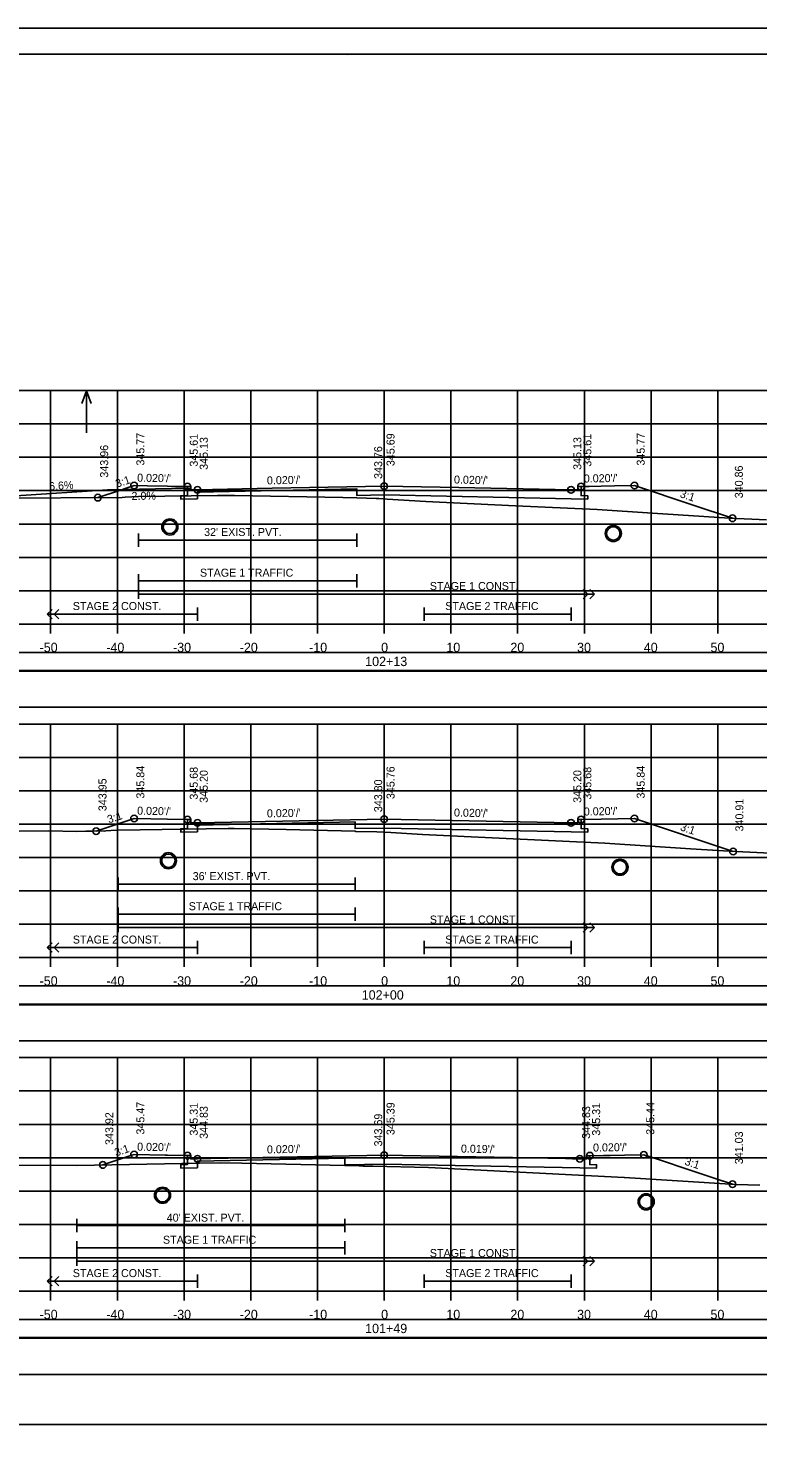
# Model space of a CAD drawing. Extents: x 1368122 to 1710785, y 373130 to 557566.
# Drawn here: x 1368635.5 to 1368744.9, y 373560 to 373770.3 of the extents above; entities that cross this region are included whole.
import ezdxf

# ---------------------------------------------------------------- set-up
doc = ezdxf.new("R2010")
doc.units = 0
for name, color, linetype in [('R_Alt Surface', 7, 'Continuous'), ('R_Axis', 7, 'Continuous'), ('R_Axis Annot', 7, 'Continuous'), ('R_Border', 7, 'Continuous'), ('R_Drive', 7, 'Continuous'), ('R_Exist Surface', 7, 'Continuous'), ('R_Fin Surface', 7, 'Continuous'), ('R_Grid', 7, 'Continuous'), ('R_No Plot', 7, 'Continuous'), ('R_Striping', 7, 'Continuous'), ('R_Water', 7, 'Continuous'), ('R_Water Annot', 7, 'Continuous'), ('R_Xsect Elev', 7, 'Continuous'), ('R_Xsect Slope', 7, 'Continuous')]:
    doc.layers.add(name, color=color, linetype=linetype)

msp = doc.modelspace()

# ---------------------------------------------------------------- linework, layer by layer
at = {"layer": 'R_Alt Surface'}
for points in [[(1368718.38, 373701.59), (1368718.38, 373700.25), (1368719.38, 373700.23), (1368719.38, 373699.73), (1368716.88, 373699.78), (1368688.88, 373700.34), (1368684.8, 373700.26), (1368684.8, 373701.26), (1368660.88, 373700.78), (1368660.88, 373699.78), (1368660.88, 373699.78), (1368658.38, 373699.73), (1368658.38, 373700.23), (1368659.38, 373700.25), (1368659.38, 373701.59)], [(1368652.05, 373694.59), (1368652.05, 373692.59)], [(1368684.8, 373694.59), (1368684.8, 373692.59)], [(1368652.05, 373693.59), (1368684.8, 373693.59)], [(1368718.38, 373651.67), (1368718.38, 373650.32), (1368719.38, 373650.3), (1368719.38, 373649.8), (1368716.88, 373649.85), (1368688.88, 373650.41), (1368684.51, 373650.33), (1368684.51, 373651.33), (1368660.88, 373650.86), (1368660.88, 373649.86), (1368660.88, 373649.85), (1368658.38, 373649.8), (1368658.38, 373650.3), (1368659.38, 373650.32), (1368659.38, 373651.67)], [(1368648.98, 373643), (1368648.98, 373641)], [(1368648.98, 373642), (1368684.51, 373642)], [(1368684.51, 373643), (1368684.51, 373641)], [(1368719.7, 373601.29), (1368719.7, 373599.95), (1368720.72, 373599.93), (1368720.72, 373599.43), (1368718.18, 373599.48), (1368688.88, 373600.04), (1368682.97, 373599.93), (1368682.97, 373600.93), (1368660.88, 373600.49), (1368660.88, 373599.49), (1368660.88, 373599.48), (1368658.38, 373599.43), (1368658.38, 373599.93), (1368659.38, 373599.95), (1368659.38, 373601.3)], [(1368642.78, 373591.8), (1368642.78, 373589.8)], [(1368642.78, 373590.8), (1368682.97, 373590.8)], [(1368682.97, 373591.8), (1368682.97, 373589.8)]]:
    msp.add_lwpolyline(points, dxfattribs=at)
for points in [[(1368539.73, 373674.03), (1368838.03, 373674.03), (1368838.03, 373676.74), (1368539.73, 373676.74)], [(1368539.73, 373668.51), (1368838.03, 373668.51), (1368838.03, 373673.92), (1368539.73, 373673.92)], [(1368539.73, 373624.03), (1368838.03, 373624.03), (1368838.03, 373626.74), (1368539.73, 373626.74)], [(1368539.73, 373618.51), (1368838.03, 373618.51), (1368838.03, 373623.92), (1368539.73, 373623.92)], [(1368539.73, 373574.03), (1368838.03, 373574.03), (1368838.03, 373576.74), (1368539.73, 373576.74)], [(1368539.73, 373568.51), (1368838.03, 373568.51), (1368838.03, 373573.92), (1368539.73, 373573.92)]]:
    msp.add_lwpolyline(points, close=True, dxfattribs=at)
at = {"layer": 'R_Axis'}
for p, q in [((1368538.88, 373680.99), (1368838.88, 373680.99)), ((1368638.88, 373679.59), (1368638.88, 373680.99)), ((1368648.88, 373679.59), (1368648.88, 373680.99)), ((1368658.88, 373679.59), (1368658.88, 373680.99)), ((1368668.88, 373679.59), (1368668.88, 373680.99)), ((1368678.88, 373679.59), (1368678.88, 373680.99)), ((1368688.88, 373679.59), (1368688.88, 373680.99)), ((1368698.88, 373679.59), (1368698.88, 373680.99)), ((1368708.88, 373679.59), (1368708.88, 373680.99)), ((1368718.88, 373679.59), (1368718.88, 373680.99)), ((1368728.88, 373679.59), (1368728.88, 373680.99)), ((1368738.88, 373679.59), (1368738.88, 373680.99)), ((1368538.88, 373630.99), (1368838.88, 373630.99)), ((1368638.88, 373629.59), (1368638.88, 373630.99)), ((1368648.88, 373629.59), (1368648.88, 373630.99)), ((1368658.88, 373629.59), (1368658.88, 373630.99)), ((1368668.88, 373629.59), (1368668.88, 373630.99)), ((1368678.88, 373629.59), (1368678.88, 373630.99)), ((1368688.88, 373629.59), (1368688.88, 373630.99)), ((1368698.88, 373629.59), (1368698.88, 373630.99)), ((1368708.88, 373629.59), (1368708.88, 373630.99)), ((1368718.88, 373629.59), (1368718.88, 373630.99)), ((1368728.88, 373629.59), (1368728.88, 373630.99)), ((1368738.88, 373629.59), (1368738.88, 373630.99)), ((1368538.88, 373580.99), (1368838.88, 373580.99)), ((1368638.88, 373579.59), (1368638.88, 373580.99)), ((1368648.88, 373579.59), (1368648.88, 373580.99)), ((1368658.88, 373579.59), (1368658.88, 373580.99)), ((1368668.88, 373579.59), (1368668.88, 373580.99)), ((1368678.88, 373579.59), (1368678.88, 373580.99)), ((1368688.88, 373579.59), (1368688.88, 373580.99)), ((1368698.88, 373579.59), (1368698.88, 373580.99)), ((1368708.88, 373579.59), (1368708.88, 373580.99)), ((1368718.88, 373579.59), (1368718.88, 373580.99)), ((1368728.88, 373579.59), (1368728.88, 373580.99)), ((1368738.88, 373579.59), (1368738.88, 373580.99))]:
    msp.add_line(p, q, dxfattribs=at)
at = {"layer": 'R_Border'}
for p, q in [((1368530.88, 373766.45), (1368847.06, 373766.45)), ((1368683.4, 373766.19), (1368683.4, 373766.19)), ((1368683.4, 373766.19), (1368683.4, 373766.19)), ((1368847.06, 373560.99), (1368530.88, 373560.99))]:
    msp.add_line(p, q, dxfattribs=at)
at = {"layer": 'R_Drive'}
for p, q in [((1368647.38, 373701.1), (1368633.68, 373700.2)), ((1368659.38, 373701.34), (1368647.38, 373701.1)), ((1368659.88, 373701.09), (1368659.38, 373701.34))]:
    msp.add_line(p, q, dxfattribs=at)
at = {"layer": 'R_Exist Surface'}
for points in [[(1368631.1, 373699.84), (1368649.61, 373699.97), (1368650.07, 373699.99), (1368652.05, 373700.09), (1368663.91, 373700.24), (1368666.45, 373700.28), (1368682.69, 373699.95), (1368684.8, 373699.9), (1368687.67, 373699.8), (1368688.07, 373699.8), (1368689.3, 373699.72), (1368695.11, 373699.35), (1368708.57, 373698.73), (1368720.8, 373698.17), (1368729.09, 373697.62), (1368740.62, 373696.87), (1368746.19, 373696.6)], [(1368634.17, 373649.95), (1368638.58, 373649.98), (1368642.78, 373649.91), (1368644.13, 373649.93), (1368645.31, 373649.92), (1368646.45, 373649.97), (1368646.88, 373649.96), (1368647.13, 373649.99), (1368647.9, 373650.06), (1368648.98, 373650.11), (1368665.5, 373650.34), (1368666.4, 373650.35), (1368674.19, 373650.17), (1368684.51, 373649.92), (1368684.65, 373649.91), (1368687.75, 373649.86), (1368689.89, 373649.72), (1368694.64, 373649.42), (1368706.1, 373648.88), (1368721.93, 373648.14), (1368734.79, 373647.31), (1368740.6, 373646.93), (1368755.01, 373646.23)], [(1368613.1, 373599.99), (1368642.78, 373599.83), (1368661.2, 373600.18), (1368664.37, 373600.24), (1368667.54, 373600.17), (1368682.97, 373599.83), (1368685.14, 373599.77), (1368685.71, 373599.74), (1368687.19, 373599.72), (1368695.53, 373599.53), (1368724.86, 373598.03), (1368724.87, 373598.02), (1368724.91, 373598.02), (1368741.59, 373596.99), (1368745.19, 373596.86)]]:
    msp.add_lwpolyline(points, dxfattribs=at)
for centre in [(1368656.75, 373695.55), (1368723.22, 373694.57), (1368656.53, 373645.51), (1368724.22, 373644.53), (1368655.65, 373595.36), (1368728.14, 373594.38)]:
    msp.add_circle(centre, 1.21, dxfattribs=at)
at = {"layer": 'R_Fin Surface'}
for points in [[(1368645.95, 373699.94), (1368648.13, 373700.67), (1368651.38, 373701.75), (1368653.38, 373701.71), (1368656.38, 373701.65), (1368657.58, 373701.63), (1368659.38, 373701.59), (1368659.58, 373701.59), (1368659.88, 373701.59), (1368659.88, 373701.29), (1368659.88, 373701.09), (1368660.28, 373701.1), (1368660.88, 373701.11), (1368672.08, 373701.34), (1368688.88, 373701.67), (1368700.08, 373701.45), (1368716.88, 373701.11), (1368717.28, 373701.1), (1368717.88, 373701.09), (1368717.88, 373701.39), (1368717.88, 373701.59), (1368718.08, 373701.59), (1368718.38, 373701.59), (1368719.58, 373701.62), (1368721.38, 373701.65), (1368723.38, 373701.69), (1368726.38, 373701.75), (1368735.19, 373698.81), (1368741.09, 373696.85)], [(1368645.7, 373649.94), (1368651.38, 373651.83), (1368656.38, 373651.73), (1368659.38, 373651.67), (1368659.88, 373651.67), (1368659.88, 373651.17), (1368660.88, 373651.19), (1368688.88, 373651.75), (1368716.88, 373651.19), (1368717.88, 373651.17), (1368717.88, 373651.67), (1368718.38, 373651.67), (1368721.38, 373651.73), (1368726.38, 373651.83), (1368741.17, 373646.9)], [(1368646.72, 373599.9), (1368651.05, 373601.35), (1368651.38, 373601.46), (1368656.02, 373601.36), (1368656.38, 373601.36), (1368659.17, 373601.3), (1368659.38, 373601.3), (1368659.84, 373601.3), (1368659.88, 373601.3), (1368659.88, 373600.83), (1368659.88, 373600.8), (1368659.95, 373600.8), (1368660.88, 373600.82), (1368662.88, 373600.86), (1368688.88, 373601.38), (1368708.09, 373601.01), (1368716.07, 373600.86), (1368717.11, 373600.84), (1368718.19, 373600.82), (1368719.06, 373600.8), (1368719.2, 373600.79), (1368719.2, 373600.87), (1368719.2, 373601.29), (1368719.28, 373601.29), (1368719.7, 373601.29), (1368721.74, 373601.33), (1368722.74, 373601.34), (1368724.89, 373601.38), (1368727.81, 373601.43), (1368729.69, 373600.8), (1368735.04, 373599.03), (1368739.68, 373597.49), (1368739.71, 373597.48), (1368739.72, 373597.48), (1368741.1, 373597.02)]]:
    msp.add_lwpolyline(points, dxfattribs=at)
at = {"layer": 'R_Grid'}
for p, q in [((1368538.88, 373715.99), (1368838.88, 373715.99)), ((1368638.88, 373680.99), (1368638.88, 373715.99)), ((1368648.88, 373680.99), (1368648.88, 373715.99)), ((1368658.88, 373680.99), (1368658.88, 373715.99)), ((1368668.88, 373680.99), (1368668.88, 373715.99)), ((1368678.88, 373680.99), (1368678.88, 373715.99)), ((1368688.88, 373680.99), (1368688.88, 373715.99)), ((1368698.88, 373680.99), (1368698.88, 373715.99)), ((1368708.88, 373680.99), (1368708.88, 373715.99)), ((1368718.88, 373680.99), (1368718.88, 373715.99)), ((1368728.88, 373680.99), (1368728.88, 373715.99)), ((1368738.88, 373680.99), (1368738.88, 373715.99)), ((1368538.88, 373710.99), (1368838.88, 373710.99)), ((1368538.88, 373705.99), (1368838.88, 373705.99)), ((1368538.88, 373700.99), (1368838.88, 373700.99)), ((1368538.88, 373695.99), (1368838.88, 373695.99)), ((1368538.88, 373690.99), (1368838.88, 373690.99)), ((1368538.88, 373685.99), (1368838.88, 373685.99)), ((1368538.88, 373680.99), (1368838.88, 373680.99)), ((1368538.88, 373665.99), (1368838.88, 373665.99)), ((1368638.88, 373630.99), (1368638.88, 373665.99)), ((1368648.88, 373630.99), (1368648.88, 373665.99)), ((1368658.88, 373630.99), (1368658.88, 373665.99)), ((1368668.88, 373630.99), (1368668.88, 373665.99)), ((1368678.88, 373630.99), (1368678.88, 373665.99)), ((1368688.88, 373630.99), (1368688.88, 373665.99)), ((1368698.88, 373630.99), (1368698.88, 373665.99)), ((1368708.88, 373630.99), (1368708.88, 373665.99)), ((1368718.88, 373630.99), (1368718.88, 373665.99)), ((1368728.88, 373630.99), (1368728.88, 373665.99)), ((1368738.88, 373630.99), (1368738.88, 373665.99)), ((1368538.88, 373660.99), (1368838.88, 373660.99)), ((1368538.88, 373655.99), (1368838.88, 373655.99)), ((1368538.88, 373650.99), (1368838.88, 373650.99)), ((1368538.88, 373645.99), (1368838.88, 373645.99)), ((1368538.88, 373640.99), (1368838.88, 373640.99)), ((1368538.88, 373635.99), (1368838.88, 373635.99)), ((1368538.88, 373630.99), (1368838.88, 373630.99)), ((1368538.88, 373615.99), (1368838.88, 373615.99)), ((1368638.88, 373580.99), (1368638.88, 373615.99)), ((1368648.88, 373580.99), (1368648.88, 373615.99)), ((1368658.88, 373580.99), (1368658.88, 373615.99)), ((1368668.88, 373580.99), (1368668.88, 373615.99)), ((1368678.88, 373580.99), (1368678.88, 373615.99)), ((1368688.88, 373580.99), (1368688.88, 373615.99)), ((1368698.88, 373580.99), (1368698.88, 373615.99)), ((1368708.88, 373580.99), (1368708.88, 373615.99)), ((1368718.88, 373580.99), (1368718.88, 373615.99)), ((1368728.88, 373580.99), (1368728.88, 373615.99)), ((1368738.88, 373580.99), (1368738.88, 373615.99)), ((1368538.88, 373610.99), (1368838.88, 373610.99)), ((1368538.88, 373605.99), (1368838.88, 373605.99)), ((1368538.88, 373600.99), (1368838.88, 373600.99)), ((1368538.88, 373595.99), (1368838.88, 373595.99)), ((1368538.88, 373590.99), (1368838.88, 373590.99)), ((1368538.88, 373585.99), (1368838.88, 373585.99)), ((1368538.88, 373580.99), (1368838.88, 373580.99))]:
    msp.add_line(p, q, dxfattribs=at)
at = {"layer": 'R_No Plot'}
msp.add_line((1368518.48, 373770.34), (1368851.81, 373770.34), dxfattribs=at)
for points in [[(1368518.47, 373770.34), (1368851.81, 373770.34), (1368851.81, 373557), (1368518.47, 373557)], [(1368764.8, 373766.45), (1368784.42, 373766.45), (1368784.42, 373756.57), (1368800.53, 373756.57), (1368823.73, 373756.57), (1368823.85, 373728.41), (1368847.06, 373728.41), (1368847.06, 373560.99), (1368530.88, 373560.99), (1368530.88, 373766.45)]]:
    msp.add_lwpolyline(points, close=True, dxfattribs=at)
for centre in [(1368651.38, 373701.75), (1368688.88, 373701.67), (1368726.38, 373701.75), (1368645.95, 373699.94), (1368659.38, 373701.59), (1368660.88, 373701.11), (1368716.88, 373701.11), (1368718.38, 373701.59), (1368741.09, 373696.85), (1368651.38, 373651.83), (1368659.38, 373651.67), (1368660.88, 373651.19), (1368688.88, 373651.75), (1368716.88, 373651.19), (1368718.38, 373651.67), (1368726.38, 373651.83), (1368645.7, 373649.94), (1368741.17, 373646.9), (1368651.38, 373601.46), (1368659.38, 373601.3), (1368660.88, 373600.82), (1368688.88, 373601.38), (1368718.19, 373600.82), (1368719.7, 373601.29), (1368727.81, 373601.43), (1368646.72, 373599.9), (1368741.1, 373597.02)]:
    msp.add_circle(centre, 0.5, dxfattribs=at)
at = {"layer": 'R_Striping'}
for p, q in [((1368719.42, 373685.49), (1368718.71, 373686.19)), ((1368718.71, 373684.78), (1368719.42, 373685.49)), ((1368720.42, 373685.49), (1368719.71, 373686.19)), ((1368719.71, 373684.78), (1368720.42, 373685.49)), ((1368638.38, 373682.49), (1368639.09, 373683.19)), ((1368638.38, 373682.49), (1368660.88, 373682.49)), ((1368639.09, 373681.78), (1368638.38, 373682.49)), ((1368639.38, 373682.49), (1368640.09, 373683.19)), ((1368640.09, 373681.78), (1368639.38, 373682.49)), ((1368719.42, 373635.49), (1368718.71, 373636.19)), ((1368718.71, 373634.78), (1368719.42, 373635.49)), ((1368720.42, 373635.49), (1368719.71, 373636.19)), ((1368719.71, 373634.78), (1368720.42, 373635.49)), ((1368638.38, 373632.49), (1368639.09, 373633.19)), ((1368639.38, 373632.49), (1368640.09, 373633.19)), ((1368638.38, 373632.49), (1368660.88, 373632.49)), ((1368639.09, 373631.78), (1368638.38, 373632.49)), ((1368640.09, 373631.78), (1368639.38, 373632.49)), ((1368719.42, 373585.49), (1368718.71, 373586.19)), ((1368718.71, 373584.78), (1368719.42, 373585.49)), ((1368720.42, 373585.49), (1368719.71, 373586.19)), ((1368719.71, 373584.78), (1368720.42, 373585.49)), ((1368638.38, 373582.49), (1368639.09, 373583.19)), ((1368638.38, 373582.49), (1368660.88, 373582.49)), ((1368639.09, 373581.78), (1368638.38, 373582.49)), ((1368639.38, 373582.49), (1368640.09, 373583.19)), ((1368640.09, 373581.78), (1368639.38, 373582.49))]:
    msp.add_line(p, q, dxfattribs=at)
for points in [[(1368652.05, 373688.49), (1368652.05, 373684.78)], [(1368652.05, 373687.49), (1368684.8, 373687.49)], [(1368684.8, 373688.49), (1368684.8, 373686.49)], [(1368652.05, 373685.49), (1368720.42, 373685.49)], [(1368660.88, 373683.49), (1368660.88, 373681.49)], [(1368694.88, 373683.49), (1368694.88, 373681.49)], [(1368716.88, 373683.49), (1368716.88, 373681.49)], [(1368694.88, 373682.49), (1368716.88, 373682.49)], [(1368648.98, 373638.49), (1368648.98, 373634.78)], [(1368648.98, 373637.49), (1368684.51, 373637.49)], [(1368684.51, 373638.49), (1368684.51, 373636.49)], [(1368648.98, 373635.49), (1368720.42, 373635.49)], [(1368660.88, 373633.49), (1368660.88, 373631.49)], [(1368694.88, 373633.49), (1368694.88, 373631.49)], [(1368716.88, 373633.49), (1368716.88, 373631.49)], [(1368694.88, 373632.49), (1368716.88, 373632.49)], [(1368642.78, 373588.49), (1368642.78, 373584.78)], [(1368642.78, 373587.49), (1368682.97, 373587.49)], [(1368682.97, 373588.49), (1368682.97, 373586.49)], [(1368642.78, 373585.49), (1368720.42, 373585.49)], [(1368660.88, 373583.49), (1368660.88, 373581.49)], [(1368694.88, 373583.49), (1368694.88, 373581.49)], [(1368694.88, 373582.49), (1368716.88, 373582.49)], [(1368716.88, 373583.49), (1368716.88, 373581.49)]]:
    msp.add_lwpolyline(points, dxfattribs=at)
at = {"layer": 'R_Water'}
for centre in [(1368656.75, 373695.55), (1368723.22, 373694.57), (1368656.53, 373645.51), (1368724.22, 373644.53), (1368655.65, 373595.36), (1368728.14, 373594.38)]:
    msp.add_circle(centre, 1, dxfattribs=at)
at = {"layer": 'R_Water Annot'}
for p, q in [((1368644.26, 373715.96), (1368643.56, 373714.04)), ((1368644.26, 373709.68), (1368644.26, 373715.96)), ((1368644.26, 373715.96), (1368644.96, 373714.04))]:
    msp.add_line(p, q, dxfattribs=at)
at = {"layer": 'R_Xsect Elev'}
for p, q in [((1368688.88, 373699.75), (1368688.88, 373709.75)), ((1368688.88, 373649.79), (1368688.88, 373659.79)), ((1368688.88, 373599.68), (1368688.88, 373609.68))]:
    msp.add_line(p, q, dxfattribs=at)

# ---------------------------------------------------------------- texts
at = {"layer": 'R_Axis Annot'}
for s, p in [('-50', (1368637.22, 373676.79)), ('-40', (1368647.22, 373676.79)), ('-30', (1368657.22, 373676.79)), ('-20', (1368667.22, 373676.79)), ('-10', (1368677.62, 373676.79)), ('0', (1368688.42, 373676.79)), ('10', (1368698.19, 373676.79)), ('20', (1368707.79, 373676.79)), ('30', (1368717.79, 373676.79)), ('40', (1368727.79, 373676.79)), ('50', (1368737.79, 373676.79)), ('102+13', (1368686.03, 373674.69)), ('-50', (1368637.22, 373626.79)), ('-40', (1368647.22, 373626.79)), ('-30', (1368657.22, 373626.79)), ('-20', (1368667.22, 373626.79)), ('-10', (1368677.62, 373626.79)), ('0', (1368688.42, 373626.79)), ('10', (1368698.19, 373626.79)), ('20', (1368707.79, 373626.79)), ('30', (1368717.79, 373626.79)), ('40', (1368727.79, 373626.79)), ('50', (1368737.79, 373626.79)), ('102+00', (1368685.51, 373624.69)), ('-50', (1368637.22, 373576.79)), ('-40', (1368647.22, 373576.79)), ('-30', (1368657.22, 373576.79)), ('-20', (1368667.22, 373576.79)), ('-10', (1368677.62, 373576.79)), ('0', (1368688.42, 373576.79)), ('10', (1368698.19, 373576.79)), ('20', (1368707.79, 373576.79)), ('30', (1368717.79, 373576.79)), ('40', (1368727.79, 373576.79)), ('50', (1368737.79, 373576.79)), ('101+49', (1368686.02, 373574.69))]:
    msp.add_text(s, height=1.4, dxfattribs=at).set_placement(p)
at = {"layer": 'R_Striping'}
for s, p in [('STAGE 1 TRAFFIC', (1368661.26, 373688.09)), ('STAGE 1 CONST.', (1368695.72, 373686.09)), ('STAGE 2 CONST.', (1368642.2, 373683.09)), ('STAGE 2 TRAFFIC', (1368698.03, 373683.09)), ('STAGE 1 TRAFFIC', (1368659.57, 373638.09)), ('STAGE 1 CONST.', (1368695.72, 373636.09)), ('STAGE 2 CONST.', (1368642.2, 373633.09)), ('STAGE 2 TRAFFIC', (1368698.03, 373633.09)), ('STAGE 1 TRAFFIC', (1368655.71, 373588.09)), ('STAGE 1 CONST.', (1368695.72, 373586.09)), ('STAGE 2 CONST.', (1368642.2, 373583.09)), ('STAGE 2 TRAFFIC', (1368698.03, 373583.09))]:
    msp.add_text(s, height=1.2, dxfattribs=at).set_placement(p)
at = {"layer": 'R_Water'}
for s, p in [("32' EXIST. PVT.", (1368661.88, 373694.19)), ("36' EXIST. PVT.", (1368660.17, 373642.6)), ("40' EXIST. PVT.", (1368656.28, 373591.4))]:
    msp.add_text(s, height=1.2, dxfattribs=at).set_placement(p)
at = {"layer": 'R_Xsect Elev'}
for s, rotation, p in [('345.77', 90, (1368652.93, 373704.75)), ('345.61', 90, (1368660.93, 373704.59)), ('345.13', 90, (1368662.43, 373704.11)), ('345.69', 90, (1368690.43, 373704.67)), ('345.13', 90, (1368718.43, 373704.11)), ('345.61', 90, (1368719.93, 373704.59)), ('345.77', 90, (1368727.93, 373704.75)), ('343.96', 90, (1368647.5, 373702.94)), ('343.76', 90, (1368688.58, 373702.75)), ('340.86', 90, (1368742.64, 373699.85)), ('6.6%', 3.776, (1368638.68, 373701.03)), ('2.0%', 1.1458, (1368651.01, 373699.58)), ('345.84', 90, (1368652.93, 373654.83)), ('345.68', 90, (1368660.93, 373654.67)), ('345.20', 90, (1368662.43, 373654.19)), ('345.76', 90, (1368690.43, 373654.75)), ('345.20', 90, (1368718.43, 373654.19)), ('345.68', 90, (1368719.93, 373654.67)), ('345.84', 90, (1368727.93, 373654.83)), ('343.95', 90, (1368647.25, 373652.94)), ('343.80', 90, (1368688.58, 373652.79)), ('340.91', 90, (1368742.72, 373649.9)), ('343.92', 90, (1368648.27, 373602.9)), ('345.47', 90, (1368652.93, 373604.46)), ('345.31', 90, (1368660.93, 373604.3)), ('344.83', 90, (1368662.43, 373603.82)), ('343.69', 90, (1368688.58, 373602.68)), ('345.39', 90, (1368690.43, 373604.38)), ('344.83', 90, (1368719.74, 373603.82)), ('345.31', 90, (1368721.25, 373604.29)), ('345.44', 90, (1368729.36, 373604.43)), ('341.03', 90, (1368742.65, 373600.02))]:
    msp.add_text(s, height=1.2, rotation=rotation, dxfattribs=at).set_placement(p)
at = {"layer": 'R_Xsect Slope'}
for s, rotation, p in [('3:1', 18.4349, (1368648.82, 373701.43)), ("0.020'/'", 358.8542, (1368651.83, 373702.34)), ("0.020'/'", 1.1458, (1368671.31, 373701.92)), ("0.020'/'", 358.8542, (1368699.33, 373702.06)), ("0.020'/'", 1.1458, (1368718.81, 373702.2)), ('3:1', 341.5651, (1368733.11, 373700.04)), ('3:1', 18.4349, (1368647.6, 373651.09)), ("0.020'/'", 358.8542, (1368651.83, 373652.42)), ("0.020'/'", 1.1458, (1368671.31, 373652)), ("0.020'/'", 358.8542, (1368699.33, 373652.14)), ("0.020'/'", 1.1458, (1368718.81, 373652.28)), ('3:1', 341.5651, (1368733.15, 373650.1)), ('3:1', 18.4349, (1368648.67, 373601.16)), ("0.020'/'", 358.8542, (1368651.83, 373602.05)), ("0.020'/'", 1.1458, (1368671.31, 373601.62)), ("0.019'/'", 358.9065, (1368700.37, 373601.76)), ("0.020'/'", 0.9569, (1368720.19, 373601.9)), ('3:1', 341.6393, (1368733.82, 373599.96))]:
    msp.add_text(s, height=1.2, rotation=rotation, dxfattribs=at).set_placement(p)

doc.saveas('drawing.dxf')
